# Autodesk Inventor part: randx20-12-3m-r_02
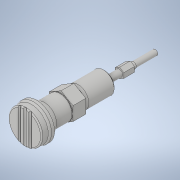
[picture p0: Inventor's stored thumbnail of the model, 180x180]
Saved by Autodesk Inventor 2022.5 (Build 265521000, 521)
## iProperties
Created: 2021-02
Part Number: randx20-12-3m-r_02
Material: 一般
Document SubType Name: Modeling
Designer: ImaoCorp
Density: 1 g/cm^3
Appearance: 既定
Author: ImaoCorp
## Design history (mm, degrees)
feature "randx20-12-3m-r_02"
node "ソリッド1"
